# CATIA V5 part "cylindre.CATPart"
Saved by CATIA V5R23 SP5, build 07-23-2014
Part number: cylindre
Definition: cylindre
Source: made
Bounding box of the stored display mesh (mm): x -70 to 70, y -159 to 29, z 0 to 244
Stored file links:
  C:\wamp\www\COURS\CONCEPTION GMP1\TITRE 01-CATIA VOLUMIQUE\05--ACTIONNEUR DE VANNE\prof\CORRECTION\Assemblage\cylindre.CATPart
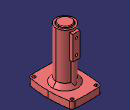
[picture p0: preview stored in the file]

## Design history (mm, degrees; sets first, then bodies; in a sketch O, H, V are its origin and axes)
Body1 "NONE" (main body)
  Solid1 "Manifold Solid #5594": solid without history
  Sketch1 on face of Solid1, origin (0, 0, 0), H (1, 0, 0), V (0, -1, 0)
    projected arc E1 centre (-50, 145) radius 7.5 from (-57.5, 145) to (-42.5, 145) ccw from edge [face of Solid1 | face of Solid1]
    projected arc E2 centre (-50, 145) radius 7.5 from (-42.5, 145) to (-57.5, 145) ccw from edge [face of Solid1 | face of Solid1]
    projected arc E3 centre (50, 145) radius 7.5 from (42.5, 145) to (57.5, 145) ccw from edge [face of Solid1 | face of Solid1]
    projected arc E4 centre (50, 145) radius 7.5 from (57.5, 145) to (42.5, 145) ccw from edge [face of Solid1 | face of Solid1]
    projected arc E5 centre (50, -15) radius 7.5 from (57.5, -15) to (42.5, -15) ccw from edge [face of Solid1 | face of Solid1]
    projected arc E6 centre (50, -15) radius 7.5 from (42.5, -15) to (57.5, -15) ccw from edge [face of Solid1 | face of Solid1]
    projected arc E7 centre (-50, -15) radius 7.5 from (-42.5, -15) to (-57.5, -15) ccw from edge [face of Solid1 | face of Solid1]
    projected arc E8 centre (-50, -15) radius 7.5 from (-57.5, -15) to (-42.5, -15) ccw from edge [face of Solid1 | face of Solid1]
  Pad1: profile Sketch1, direction (0, 0, -1), up to face of Solid1
  Sketch2 on face of Solid1, origin (-12.7812, -145.388, 0), H (1, 0, 0), V (0, -1, 0)
    point P1 (-37.2188, -0.388)
    reference projected arc E1 centre (-37.2188, -0.388) radius 12.5 from (-37.9681, 12.0895) to (-49.501, 1.9353) ccw from edge [face of Solid1 | face of Solid1]
    concentricity: P1 E1
  Hole1: placed by Sketch2, at (-50, -145, 0) direction (0, 0, 1), diameter 13, through (limit type 6)
  Sketch3 on face of Solid1, origin (0, 0, 0), H (1, 0, 0), V (0, -1, 0)
    point P1 (50, 145)
    point P2 (50, -15)
    point P3 (-50, -15)
    reference projected arc E1 centre (-50, -15) radius 12.5 from (-62.2822, -17.3233) to (-50.7493, -27.4775) ccw from edge [face of Solid1 | face of Solid1]
    reference projected arc E2 centre (50, -15) radius 12.5 from (50.7493, -27.4775) to (62.2822, -17.3233) ccw from edge [face of Solid1 | face of Solid1]
    reference projected arc E3 centre (50, 145) radius 12.5 from (62.2822, 147.3233) to (50.7493, 157.4775) ccw from edge [face of Solid1 | face of Solid1]
    concentricity: P3 E1, P2 E2, P1 E3
  UserPattern1: of Hole1, copies 4, at the points of Sketch3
